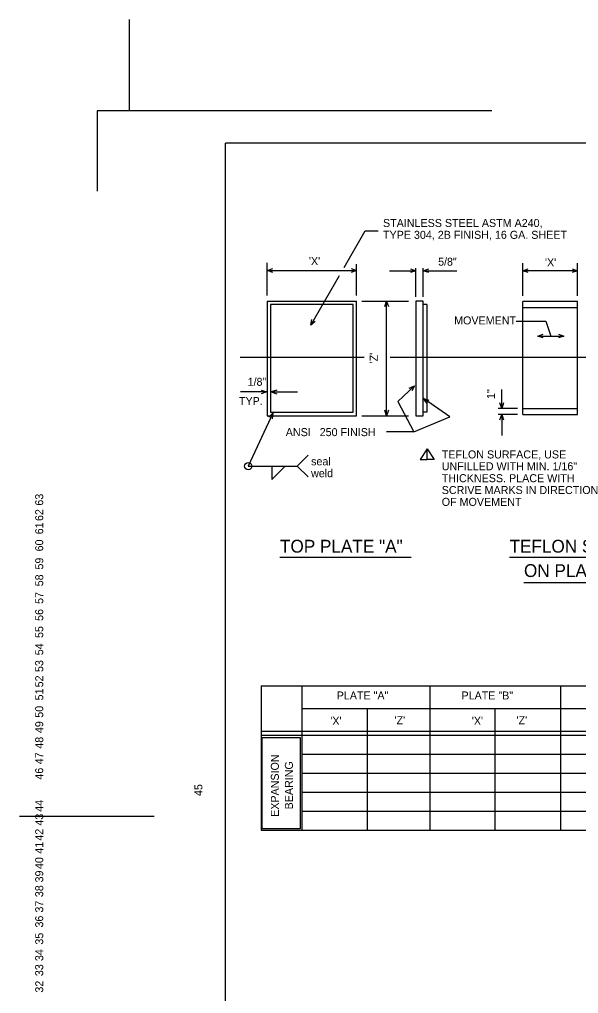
# Model space of a CAD drawing. Extents: x -1.11 to 2, y -1.43 to 1.11.
# Drawn here: x -1.114 to -0.387, y -0.154 to 1.113 of the extents above; entities that cross this region are included whole.
import ezdxf

# ---------------------------------------------------------------- set-up
doc = ezdxf.new("R2010")
doc.units = 0
for name, color, linetype in [('Level 1', 7, 'Continuous'), ('Level 2', 7, 'Continuous'), ('Level 32', 7, 'Continuous'), ('Level 33', 7, 'Continuous'), ('Level 34', 7, 'Continuous'), ('Level 35', 7, 'Continuous'), ('Level 36', 7, 'Continuous'), ('Level 37', 7, 'Continuous'), ('Level 38', 7, 'Continuous'), ('Level 39', 7, 'Continuous'), ('Level 40', 7, 'Continuous'), ('Level 41', 7, 'Continuous'), ('Level 42', 7, 'Continuous'), ('Level 43', 7, 'Continuous'), ('Level 44', 7, 'Continuous'), ('Level 45', 7, 'Continuous'), ('Level 46', 7, 'Continuous'), ('Level 47', 7, 'Continuous'), ('Level 48', 7, 'Continuous'), ('Level 49', 7, 'Continuous'), ('Level 50', 7, 'Continuous'), ('Level 51', 7, 'Continuous'), ('Level 52', 7, 'Continuous'), ('Level 53', 7, 'Continuous'), ('Level 54', 7, 'Continuous'), ('Level 55', 7, 'Continuous'), ('Level 56', 7, 'Continuous'), ('Level 57', 7, 'Continuous'), ('Level 58', 7, 'Continuous'), ('Level 59', 7, 'Continuous'), ('Level 60', 7, 'Continuous'), ('Level 61', 7, 'Continuous'), ('Level 62', 7, 'Continuous'), ('Level 63', 7, 'Continuous')]:
    doc.layers.add(name, color=color, linetype=linetype)

msp = doc.modelspace()

# ---------------------------------------------------------------- linework, layer by layer
at = {"layer": 'Level 1'}
for p, q in [((-0.4998, 0.9937), (-1.0128, 0.9937)), ((-1.0128, 0.9937), (-1.0128, 0.8892)), ((-0.846, -0.7994), (-0.846, 0.952)), ((1.7708, 0.952), (-0.846, 0.952))]:
    msp.add_line(p, q, dxfattribs=at)
at = {"layer": 'Level 2'}
for p, q in [((-0.9711, 0.9937), (-0.9711, 1.1127)), ((-0.6919, 0.7901), (-0.6646, 0.8377)), ((-0.6646, 0.8377), (-0.6477, 0.8377)), ((-0.7919, 0.7536), (-0.7919, 0.7961)), ((-0.7919, 0.7863), (-0.6758, 0.7863)), ((-0.6758, 0.7536), (-0.6758, 0.7943)), ((-0.6328, 0.7859), (-0.5988, 0.7859)), ((-0.5988, 0.7518), (-0.5988, 0.7894)), ((-0.589, 0.7518), (-0.589, 0.7894)), ((-0.589, 0.7859), (-0.5452, 0.7859)), ((-0.4597, 0.7532), (-0.4597, 0.7957)), ((-0.3885, 0.7859), (-0.4597, 0.7859)), ((-0.3885, 0.7532), (-0.3885, 0.7957)), ((-0.735, 0.715), (-0.6978, 0.7798)), ((-0.7919, 0.7465), (-0.7919, 0.5974)), ((-0.7919, 0.7465), (-0.6758, 0.7465)), ((-0.6802, 0.7421), (-0.7875, 0.7421)), ((-0.7875, 0.7421), (-0.7875, 0.6018)), ((-0.6802, 0.6018), (-0.6802, 0.7421)), ((-0.6758, 0.5974), (-0.6758, 0.7465)), ((-0.6688, 0.7465), (-0.6084, 0.7465)), ((-0.6367, 0.5974), (-0.6367, 0.7465)), ((-0.589, 0.7465), (-0.5988, 0.7465)), ((-0.5988, 0.7465), (-0.5988, 0.5974)), ((-0.589, 0.5974), (-0.589, 0.7465)), ((-0.5843, 0.7421), (-0.589, 0.7421)), ((-0.5843, 0.7421), (-0.5843, 0.6018)), ((-0.3885, 0.7461), (-0.4597, 0.7461)), ((-0.4597, 0.5989), (-0.4597, 0.7461)), ((-0.4597, 0.7382), (-0.3885, 0.7382)), ((-0.3885, 0.5989), (-0.3885, 0.7461)), ((-0.4681, 0.7204), (-0.4297, 0.7204)), ((-0.4297, 0.7204), (-0.4233, 0.701)), ((-0.4402, 0.701), (-0.4063, 0.701)), ((-0.8272, 0.6733), (-0.666, 0.6733)), ((-0.632, 0.6733), (-0.3766, 0.6733)), ((-0.6005, 0.6363), (-0.6221, 0.6159)), ((-0.7925, 0.6283), (-0.8266, 0.6283)), ((-0.7996, 0.6307), (-0.7925, 0.6283)), ((-0.7925, 0.6283), (-0.7996, 0.6258)), ((-0.7796, 0.6307), (-0.7867, 0.6283)), ((-0.7867, 0.6283), (-0.7526, 0.6283)), ((-0.7867, 0.6283), (-0.7796, 0.6258)), ((-0.487, 0.6068), (-0.487, 0.6315)), ((-0.6221, 0.6159), (-0.6013, 0.5763)), ((-0.5544, 0.5957), (-0.5888, 0.6197)), ((-0.7847, 0.6008), (-0.8165, 0.5318)), ((-0.7919, 0.5974), (-0.6758, 0.5974)), ((-0.7875, 0.6018), (-0.6802, 0.6018)), ((-0.6688, 0.5974), (-0.6084, 0.5974)), ((-0.6013, 0.5763), (-0.5544, 0.5957)), ((-0.5988, 0.5974), (-0.589, 0.5974)), ((-0.5843, 0.6018), (-0.589, 0.6018)), ((-0.4667, 0.6068), (-0.4915, 0.6068)), ((-0.4667, 0.5989), (-0.4915, 0.5989)), ((-0.487, 0.5989), (-0.487, 0.5715)), ((-0.4597, 0.6068), (-0.3885, 0.6068)), ((-0.4597, 0.5989), (-0.3885, 0.5989)), ((-0.6013, 0.5763), (-0.6369, 0.5763)), ((-0.7528, 0.5318), (-0.7387, 0.5459)), ((-0.8165, 0.5318), (-0.7528, 0.5318)), ((-0.7859, 0.5316), (-0.7859, 0.5144)), ((-0.7859, 0.5144), (-0.769, 0.5313)), ((-0.7528, 0.5318), (-0.7388, 0.5178)), ((-0.7753, 0.4134), (-0.6048, 0.4134)), ((-0.4769, 0.4134), (-0.2846, 0.4134)), ((-0.4581, 0.3805), (-0.3027, 0.3805)), ((-0.7998, 0.246), (0.4953, 0.246)), ((-0.7998, 0.246), (-0.7998, 0.0583)), ((-0.7468, 0.246), (-0.7468, 0.0583)), ((-0.5803, 0.246), (-0.5803, 0.0583)), ((-0.4108, 0.246), (-0.4108, 0.0583)), ((-0.7468, 0.2164), (0.0903, 0.2164)), ((-0.6621, 0.2164), (-0.6621, 0.0583)), ((-0.4961, 0.2164), (-0.4961, 0.0583)), ((-0.7998, 0.1869), (0.4953, 0.1869)), ((-0.7998, 0.182), (-0.7468, 0.182)), ((-0.7521, 0.1869), (-0.7468, 0.1869)), ((-0.7468, 0.182), (0.4953, 0.182)), ((-0.7468, 0.1573), (0.4953, 0.1573)), ((-0.7468, 0.1325), (0.4953, 0.1325)), ((-0.7468, 0.1078), (0.4953, 0.1078)), ((-0.7468, 0.083), (0.4953, 0.083)), ((-0.7998, 0.0583), (0.4953, 0.0583))]:
    msp.add_line(p, q, dxfattribs=at)
for points in [[(-0.7848, 0.7838), (-0.7919, 0.7863), (-0.7848, 0.7887)], [(-0.6828, 0.7887), (-0.6758, 0.7863), (-0.6828, 0.7838)], [(-0.6058, 0.7883), (-0.5988, 0.7859), (-0.6058, 0.7835)], [(-0.5819, 0.7835), (-0.589, 0.7859), (-0.5819, 0.7883)], [(-0.4526, 0.7835), (-0.4597, 0.7859), (-0.4526, 0.7883)], [(-0.3956, 0.7883), (-0.3885, 0.7859), (-0.3956, 0.7835)], [(-0.6391, 0.7394), (-0.6367, 0.7465), (-0.6343, 0.7394)], [(-0.7295, 0.7201), (-0.735, 0.715), (-0.7338, 0.7224)], [(-0.4331, 0.6986), (-0.4402, 0.701), (-0.4331, 0.7035)], [(-0.4134, 0.7035), (-0.4063, 0.701), (-0.4134, 0.6986)], [(-0.6073, 0.6332), (-0.6005, 0.6363), (-0.6039, 0.6297)], [(-0.5844, 0.6137), (-0.5888, 0.6197), (-0.5817, 0.6177)], [(-0.4846, 0.6139), (-0.487, 0.6068), (-0.4895, 0.6139)], [(-0.7898, 0.5954), (-0.7847, 0.6008), (-0.7854, 0.5934)], [(-0.6343, 0.6045), (-0.6367, 0.5974), (-0.6391, 0.6045)], [(-0.4895, 0.5918), (-0.487, 0.5989), (-0.4846, 0.5918)], [(-0.5839, 0.5542), (-0.5931, 0.5402), (-0.5839, 0.5402)], [(-0.5839, 0.5542), (-0.5748, 0.5402), (-0.5839, 0.5402)]]:
    msp.add_lwpolyline(points, dxfattribs=at)
for points in [[(-0.5839, 0.5542), (-0.5748, 0.5402), (-0.5839, 0.5402)], [(-0.7983, 0.1789), (-0.749, 0.1789), (-0.749, 0.0601), (-0.7983, 0.0601)]]:
    msp.add_lwpolyline(points, close=True, dxfattribs=at)
msp.add_circle((-0.8165, 0.5318), 0.00472, dxfattribs=at)
at = {"layer": 'Level 37'}
msp.add_line((-0.9389, 0.0763), (-1.114, 0.0763), dxfattribs=at)

# ---------------------------------------------------------------- texts
at = {"layer": 'Level 2'}
for s, height, p in [('STAINLESS STEEL ASTM A240,', 0.010417, (-0.6414, 0.8428)), ('TYPE 304, 2B FINISH, 16 GA. SHEET', 0.010417, (-0.6414, 0.8274)), ("'X'", 0.01042, (-0.7377, 0.7933)), ('5/8"', 0.01033, (-0.5697, 0.7925)), ("'X'", 0.01042, (-0.4308, 0.7916)), ('MOVEMENT', 0.01042, (-0.5489, 0.7161)), ('1/8"', 0.01033, (-0.8173, 0.6363)), ('TYP.', 0.01033, (-0.8285, 0.6113)), ('ANSI   250 FINISH', 0.010417, (-0.7678, 0.5708)), ('TEFLON SURFACE, USE', 0.010417, (-0.565, 0.5418)), ('seal', 0.01042, (-0.7349, 0.5328)), ('UNFILLED WITH MIN. 1/16"', 0.010417, (-0.565, 0.5264)), ('weld', 0.01042, (-0.7349, 0.5174)), ('THICKNESS. PLACE WITH', 0.010417, (-0.565, 0.5109)), ('SCRIVE MARKS IN DIRECTION', 0.010417, (-0.565, 0.4955)), ('OF MOVEMENT', 0.010417, (-0.565, 0.4801)), ('TOP PLATE "A"', 0.016667, (-0.7753, 0.4193)), ('TEFLON SURFACE', 0.016667, (-0.4769, 0.4193)), ('ON PLATE "B"', 0.016667, (-0.4581, 0.3876)), ('PLATE "A"', 0.0104, (-0.7015, 0.2283)), ('PLATE "B"', 0.0104, (-0.5393, 0.2283)), ("'X'", 0.0104, (-0.7099, 0.1954)), ("'Z'", 0.0104, (-0.6264, 0.1962)), ("'X'", 0.0104, (-0.5259, 0.1954)), ("'Z'", 0.0104, (-0.4678, 0.1962))]:
    msp.add_text(s, height=height, dxfattribs=at).set_placement(p)
for s, height, p in [("'Z'", 0.01042, (-0.6481, 0.6654)), ('1"', 0.01042, (-0.4959, 0.6191)), ('EXPANSION', 0.0104, (-0.7768, 0.0757)), ('BEARING', 0.0104, (-0.7585, 0.0854))]:
    msp.add_text(s, height=height, rotation=90, dxfattribs=at).set_placement(p)
at = {"layer": 'Level 32'}
msp.add_text('32', height=0.01041, rotation=90, dxfattribs=at).set_placement((-1.0831, -0.1529))
at = {"layer": 'Level 33'}
msp.add_text('33', height=0.01041, rotation=90, dxfattribs=at).set_placement((-1.0831, -0.1315))
at = {"layer": 'Level 34'}
msp.add_text('34', height=0.01041, rotation=90, dxfattribs=at).set_placement((-1.0831, -0.1119))
at = {"layer": 'Level 35'}
msp.add_text('35', height=0.01041, rotation=90, dxfattribs=at).set_placement((-1.0831, -0.0905))
at = {"layer": 'Level 36'}
msp.add_text('36', height=0.01041, rotation=90, dxfattribs=at).set_placement((-1.0831, -0.0683))
at = {"layer": 'Level 37'}
msp.add_text('37', height=0.01041, rotation=90, dxfattribs=at).set_placement((-1.0831, -0.0488))
at = {"layer": 'Level 38'}
msp.add_text('38', height=0.01041, rotation=90, dxfattribs=at).set_placement((-1.0831, -0.0288))
at = {"layer": 'Level 39'}
msp.add_text('39', height=0.01041, rotation=90, dxfattribs=at).set_placement((-1.0831, -0.0096))
at = {"layer": 'Level 40'}
msp.add_text('40', height=0.01041, rotation=90, dxfattribs=at).set_placement((-1.0831, 0.0078))
at = {"layer": 'Level 41'}
msp.add_text('41', height=0.01041, rotation=90, dxfattribs=at).set_placement((-1.0831, 0.0277))
at = {"layer": 'Level 42'}
msp.add_text('42', height=0.01041, rotation=90, dxfattribs=at).set_placement((-1.0831, 0.0447))
at = {"layer": 'Level 43'}
msp.add_text('43', height=0.01041, rotation=90, dxfattribs=at).set_placement((-1.0831, 0.0643))
at = {"layer": 'Level 44'}
msp.add_text('44', height=0.01041, rotation=90, dxfattribs=at).set_placement((-1.0831, 0.0823))
at = {"layer": 'Level 45'}
msp.add_text('45', height=0.01041, rotation=90, dxfattribs=at).set_placement((-0.8762, 0.1027))
at = {"layer": 'Level 46'}
msp.add_text('46', height=0.01041, rotation=90, dxfattribs=at).set_placement((-1.0831, 0.1241))
at = {"layer": 'Level 47'}
msp.add_text('47', height=0.01041, rotation=90, dxfattribs=at).set_placement((-1.0831, 0.144))
at = {"layer": 'Level 48'}
msp.add_text('48', height=0.01041, rotation=90, dxfattribs=at).set_placement((-1.0831, 0.1643))
at = {"layer": 'Level 49'}
msp.add_text('49', height=0.01041, rotation=90, dxfattribs=at).set_placement((-1.0831, 0.1846))
at = {"layer": 'Level 50'}
msp.add_text('50', height=0.01041, rotation=90, dxfattribs=at).set_placement((-1.0831, 0.2046))
at = {"layer": 'Level 51'}
msp.add_text('51', height=0.01041, rotation=90, dxfattribs=at).set_placement((-1.0831, 0.2271))
at = {"layer": 'Level 52'}
msp.add_text('52', height=0.01041, rotation=90, dxfattribs=at).set_placement((-1.0831, 0.2441))
at = {"layer": 'Level 53'}
msp.add_text('53', height=0.01041, rotation=90, dxfattribs=at).set_placement((-1.0831, 0.264))
at = {"layer": 'Level 54'}
msp.add_text('54', height=0.01041, rotation=90, dxfattribs=at).set_placement((-1.0831, 0.2858))
at = {"layer": 'Level 55'}
msp.add_text('55', height=0.01041, rotation=90, dxfattribs=at).set_placement((-1.0831, 0.3083))
at = {"layer": 'Level 56'}
msp.add_text('56', height=0.01041, rotation=90, dxfattribs=at).set_placement((-1.0831, 0.3305))
at = {"layer": 'Level 57'}
msp.add_text('57', height=0.01041, rotation=90, dxfattribs=at).set_placement((-1.0831, 0.3526))
at = {"layer": 'Level 58'}
msp.add_text('58', height=0.01041, rotation=90, dxfattribs=at).set_placement((-1.0831, 0.3755))
at = {"layer": 'Level 59'}
msp.add_text('59', height=0.01041, rotation=90, dxfattribs=at).set_placement((-1.0831, 0.3973))
at = {"layer": 'Level 60'}
msp.add_text('60', height=0.01041, rotation=90, dxfattribs=at).set_placement((-1.0831, 0.4209))
at = {"layer": 'Level 61'}
msp.add_text('61', height=0.01041, rotation=90, dxfattribs=at).set_placement((-1.0831, 0.4431))
at = {"layer": 'Level 62'}
msp.add_text('62', height=0.01041, rotation=90, dxfattribs=at).set_placement((-1.0831, 0.4604))
at = {"layer": 'Level 63'}
msp.add_text('63', height=0.01041, rotation=90, dxfattribs=at).set_placement((-1.0831, 0.4804))

doc.saveas('drawing.dxf')
